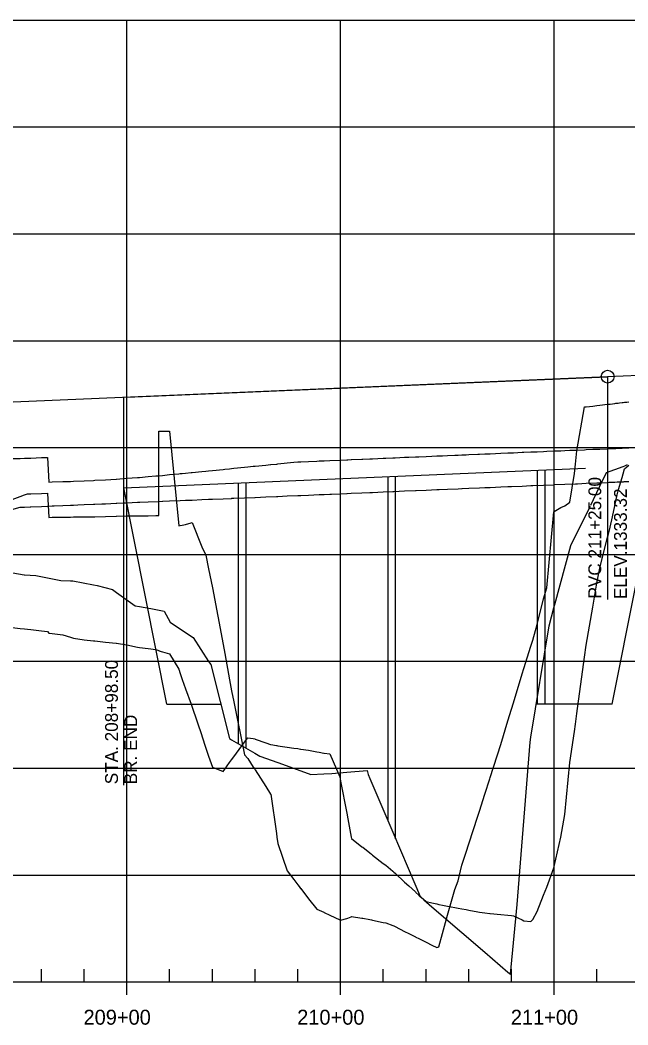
# Model space of a CAD drawing. Extents: x 1371206 to 1374178, y 379328 to 381511.
# Drawn here: x 1372094.6 to 1372379.1, y 379328.3 to 379798.4 of the extents above; entities that cross this region are included whole.
import ezdxf

# ---------------------------------------------------------------- set-up
doc = ezdxf.new("R2010")
doc.units = 0
for name, color, linetype in [('30', 7, 'Continuous'), ('37', 7, 'Continuous'), ('BRIDGE', 7, 'Continuous'), ('No Plot', 7, 'Continuous'), ('R_Exist Surface', 7, 'Continuous'), ('R_Profile Work Left', 7, 'Continuous'), ('R_Profile Work Right', 7, 'Continuous'), ('R_Vert Alg', 7, 'Continuous'), ('R_Vert Alg Annot', 7, 'Continuous')]:
    doc.layers.add(name, color=color, linetype=linetype)

msp = doc.modelspace()

# ---------------------------------------------------------------- linework, layer by layer
at = {"layer": '37'}
for p, q in [((1371244.63, 379798.35), (1374144.63, 379798.35)), ((1371244.63, 379798.35), (1374144.63, 379798.35)), ((1372144.63, 379348.35), (1372144.63, 379798.35)), ((1372244.63, 379348.35), (1372244.63, 379798.35)), ((1372344.63, 379348.35), (1372344.63, 379798.35)), ((1371244.63, 379748.35), (1374144.63, 379748.35)), ((1371244.63, 379698.35), (1374144.63, 379698.35)), ((1371244.63, 379648.35), (1374144.63, 379648.35)), ((1371244.63, 379598.35), (1372944.63, 379598.35)), ((1371244.63, 379598.35), (1374144.63, 379598.35)), ((1371244.63, 379548.35), (1374144.63, 379548.35)), ((1371244.63, 379498.35), (1374144.63, 379498.35)), ((1371244.63, 379448.35), (1374144.63, 379448.35)), ((1371244.63, 379398.35), (1374144.63, 379398.35)), ((1372104.63, 379348.35), (1372104.63, 379354.35)), ((1372124.63, 379348.35), (1372124.63, 379354.35)), ((1372164.63, 379348.35), (1372164.63, 379354.35)), ((1372184.63, 379348.35), (1372184.63, 379354.35)), ((1372204.63, 379348.35), (1372204.63, 379354.35)), ((1372224.63, 379348.35), (1372224.63, 379354.35)), ((1372264.63, 379348.35), (1372264.63, 379354.35)), ((1372284.63, 379348.35), (1372284.63, 379354.35)), ((1372304.63, 379348.35), (1372304.63, 379354.35)), ((1372324.63, 379348.35), (1372324.63, 379354.35)), ((1372364.63, 379348.35), (1372364.63, 379354.35)), ((1371244.63, 379348.35), (1374144.63, 379348.35)), ((1372144.63, 379342.35), (1372144.63, 379348.35)), ((1372244.63, 379342.35), (1372244.63, 379348.35)), ((1372344.63, 379342.35), (1372344.63, 379348.35))]:
    msp.add_line(p, q, dxfattribs=at)
at = {"layer": 'BRIDGE'}
for p, q in [((1372144.63, 379621.98), (1372369.63, 379631.52)), ((1372143.13, 379579.48), (1372359.26, 379588.65)), ((1372163.36, 379478.35), (1372143.13, 379579.49)), ((1372143.13, 379440.44), (1372143.13, 379579.3)), ((1372163.36, 379478.35), (1372188.56, 379478.35)), ((1372371.78, 379478.35), (1372336.3, 379478.35))]:
    msp.add_line(p, q, dxfattribs=at)
for points in [[(1372143.13, 379579.49), (1372143.13, 379621.93)], [(1372144.63, 379576.49), (1372144.63, 379621.49)], [(1372336.88, 379478.35), (1372336.88, 379587.7)], [(1372340.38, 379478.35), (1372340.38, 379587.85)], [(1372371.78, 379478.35), (1372394.13, 379590.12)], [(1372196.88, 379459.82), (1372196.88, 379581.76)], [(1372200.38, 379457.78), (1372200.38, 379581.91)], [(1372266.88, 379423.52), (1372266.88, 379584.73)], [(1372270.38, 379415.35), (1372270.38, 379584.88)]]:
    msp.add_lwpolyline(points, dxfattribs=at)
at = {"layer": 'No Plot'}
msp.add_lwpolyline([(1372361.76, 379571.45), (1372363.08, 379574.13), (1372366.06, 379580.34), (1372369.11, 379586.69), (1372376.84, 379589.57), (1372377.62, 379589.87), (1372379.01, 379590.36)], dxfattribs=at)
at = {"layer": 'R_Exist Surface'}
msp.add_lwpolyline([(1372085.91, 379540.75), (1372096.5, 379538.79), (1372096.68, 379538.78), (1372102.04, 379538.57), (1372107.46, 379537.4), (1372113.63, 379536.15), (1372118.23, 379535.99), (1372119.39, 379535.97), (1372129.01, 379534.19), (1372130.72, 379533.89), (1372137.9, 379531.94), (1372139.78, 379530.58), (1372148.49, 379524.37), (1372150.56, 379523.96), (1372155.76, 379522.99), (1372161.33, 379521.94), (1372162.1, 379521.81), (1372164.85, 379516.73), (1372172.11, 379511.83), (1372175.66, 379509.47), (1372182.88, 379498.31), (1372183.85, 379496.83), (1372192.67, 379462.26), (1372193.66, 379461.69), (1372204.43, 379455.43), (1372206.89, 379454), (1372215.21, 379451), (1372225.98, 379447.1), (1372230.65, 379445.41), (1372236.76, 379445.68), (1372240.52, 379445.84), (1372247.53, 379446.46), (1372257.11, 379447.28), (1372257.5, 379445.38), (1372258.31, 379443.5), (1372269.09, 379418.38), (1372279.86, 379393.16), (1372281.95, 379388.25), (1372282.56, 379387.86), (1372283.56, 379386.73), (1372286.05, 379384.61), (1372290.64, 379380.7), (1372301.41, 379371.49), (1372312.19, 379362.25), (1372322.96, 379352.98), (1372324.14, 379351.97), (1372327.31, 379384.57), (1372333.36, 379460.54), (1372333.74, 379462.8), (1372342.34, 379514.98), (1372344.51, 379523.35), (1372344.94, 379525), (1372352.44, 379552.54), (1372355.29, 379558.32), (1372361.55, 379571.02)], dxfattribs=at)
at = {"layer": 'R_Profile Work Left'}
for points in [[(1372354.19, 379586.29), (1372354.63, 379590.53), (1372355.29, 379596.85), (1372358.74, 379617.35), (1372359.63, 379617.45), (1372362.69, 379617.8), (1372364.63, 379618.02), (1372366.06, 379618.19), (1372369.63, 379618.61), (1372369.81, 379618.63), (1372370.76, 379618.74), (1372371.88, 379618.87), (1372373.01, 379619.01), (1372373.46, 379619.06), (1372374.13, 379619.14), (1372374.63, 379619.2), (1372375.26, 379619.27), (1372376.38, 379619.4), (1372376.84, 379619.46), (1372377.51, 379619.54), (1372378.63, 379619.67), (1372379.63, 379619.79)], [(1372089.63, 379573.53), (1372094.63, 379575.45), (1372096.68, 379576.23), (1372098.04, 379576.75), (1372099.63, 379576.79), (1372104.63, 379576.91), (1372107.46, 379576.97), (1372108.13, 379565.71), (1372108.15, 379565.71), (1372109.63, 379565.73), (1372114.63, 379565.8), (1372118.23, 379565.86), (1372119.63, 379565.89), (1372124.63, 379565.96), (1372129.01, 379566.02), (1372129.63, 379566.02), (1372134.63, 379566.18), (1372139.63, 379566.32), (1372139.78, 379566.32), (1372144.63, 379566.38), (1372149.63, 379566.43), (1372150.56, 379566.45), (1372154.63, 379566.49), (1372158.11, 379566.56), (1372159.5, 379566.62), (1372159.63, 379606.03)], [(1372159.63, 379606.03), (1372161.33, 379606.06), (1372164.63, 379606.09)], [(1372164.63, 379606.09), (1372168.88, 379561.74), (1372169.63, 379561.9), (1372170.57, 379562.1), (1372172.11, 379562.43), (1372174.63, 379563.08), (1372175.16, 379563.28), (1372179.63, 379551.95)], [(1372089.63, 379569.06), (1372094.63, 379570.4), (1372096.68, 379570.49), (1372096.73, 379570.49), (1372099.38, 379570.61), (1372099.63, 379570.62), (1372104.63, 379570.83), (1372107.46, 379570.95), (1372107.51, 379570.95), (1372109.63, 379571.04), (1372110.54, 379571.08), (1372114.63, 379571.25), (1372118.23, 379571.41), (1372118.29, 379571.41), (1372119.63, 379571.46), (1372121.7, 379571.55), (1372124.63, 379571.68), (1372129.01, 379571.86), (1372129.07, 379571.87), (1372129.63, 379571.89), (1372132.86, 379572.03), (1372134.63, 379572.1), (1372139.63, 379572.31), (1372139.78, 379572.32), (1372139.85, 379572.32), (1372143.13, 379572.46), (1372144.02, 379572.5), (1372144.63, 379572.52), (1372149.63, 379572.74), (1372150.56, 379572.78), (1372150.63, 379572.78), (1372154.63, 379572.95), (1372159.63, 379573.16), (1372161.33, 379573.23), (1372161.41, 379573.24), (1372164.55, 379573.37), (1372164.63, 379573.37), (1372169.63, 379573.58), (1372172.11, 379573.69), (1372172.19, 379573.69), (1372174.63, 379573.8), (1372175.16, 379573.82), (1372179.63, 379574.01), (1372182.88, 379574.15), (1372182.98, 379574.15), (1372184.63, 379574.22), (1372189.63, 379574.43), (1372193.66, 379574.6), (1372193.76, 379574.61), (1372194.63, 379574.64), (1372199.63, 379574.86), (1372204.43, 379575.06), (1372204.54, 379575.06), (1372204.63, 379575.07), (1372209.63, 379575.28), (1372214.63, 379575.49), (1372215.21, 379575.52), (1372215.32, 379575.52), (1372219.63, 379575.7), (1372224.63, 379575.92), (1372225.18, 379575.94), (1372225.98, 379575.97), (1372226.1, 379575.98), (1372229.63, 379576.13), (1372234.63, 379576.34), (1372236.76, 379576.43), (1372236.88, 379576.44), (1372239.63, 379576.55), (1372240.46, 379576.59), (1372244.63, 379576.76), (1372247.53, 379576.89), (1372247.66, 379576.89), (1372249.63, 379576.98), (1372254.63, 379577.19), (1372258.31, 379577.34), (1372258.44, 379577.35), (1372259.63, 379577.4), (1372264.63, 379577.61), (1372269.09, 379577.8), (1372269.23, 379577.81), (1372269.63, 379577.82), (1372274.63, 379578.04), (1372279.63, 379578.25), (1372279.86, 379578.26), (1372280.01, 379578.26), (1372284.63, 379578.46), (1372289.63, 379578.67), (1372290.64, 379578.72), (1372290.79, 379578.72), (1372294.63, 379578.88), (1372299.63, 379579.1), (1372301.41, 379579.17), (1372301.57, 379579.18), (1372304.63, 379579.31), (1372309.63, 379579.52), (1372312.19, 379579.63), (1372312.35, 379579.64), (1372314.63, 379579.73), (1372319.63, 379579.94), (1372322.96, 379580.09), (1372323.13, 379580.09), (1372324.63, 379580.16), (1372329.63, 379580.37), (1372333.74, 379580.54), (1372333.91, 379580.55), (1372334.63, 379580.58), (1372339.63, 379580.79), (1372344.51, 379581), (1372344.63, 379581), (1372344.69, 379581.01), (1372349.63, 379581.22), (1372354.63, 379581.43), (1372355.29, 379581.46), (1372355.48, 379581.46), (1372359.63, 379581.64), (1372364.63, 379581.85), (1372366.06, 379581.91), (1372366.26, 379581.92), (1372369.63, 379582.06), (1372370.43, 379582.1), (1372370.75, 379582.11), (1372371.86, 379582.16), (1372372.97, 379582.21), (1372374.09, 379582.26), (1372374.63, 379582.29), (1372375.2, 379582.31), (1372376.32, 379582.37), (1372376.84, 379582.39), (1372377.04, 379582.4), (1372377.43, 379582.42), (1372378.55, 379582.48), (1372379.63, 379582.53)], [(1372341.16, 379532.67), (1372344.51, 379568.37), (1372344.63, 379568.44), (1372347.67, 379570.34), (1372349.63, 379571.03), (1372351.92, 379572.85), (1372354.19, 379586.29)], [(1372179.63, 379551.95), (1372179.65, 379551.92), (1372181.64, 379548.05), (1372182.88, 379541.63), (1372184.63, 379532.67), (1372189.63, 379506.17), (1372190.42, 379501.95), (1372192.71, 379489.67), (1372193.66, 379484.57), (1372194.63, 379479.38), (1372199.63, 379454.67), (1372201.18, 379452.88), (1372203.77, 379448.86), (1372204.43, 379447.83), (1372204.63, 379447.53), (1372209.63, 379439.77), (1372211.91, 379436.24), (1372211.95, 379436.18), (1372214.63, 379417.74), (1372214.84, 379416.02), (1372215.21, 379413.06), (1372219.63, 379400.41), (1372222.72, 379396.33), (1372224.63, 379393.8), (1372225.18, 379393.08), (1372225.91, 379392.1), (1372225.98, 379392.01), (1372229.63, 379387.16), (1372233.48, 379382.44), (1372234.63, 379381.91), (1372236.76, 379380.92), (1372236.98, 379380.82), (1372239.63, 379379.59), (1372244.25, 379377.45), (1372244.63, 379377.27), (1372247.53, 379378.05), (1372248.05, 379378.26), (1372249.63, 379378.89), (1372249.74, 379378.93), (1372254.63, 379378.26), (1372255.02, 379378.18), (1372258.31, 379377.51), (1372259.12, 379377.35), (1372259.63, 379377.24), (1372264.63, 379376.22), (1372265.79, 379375.98), (1372269.09, 379374.81), (1372269.63, 379374.54), (1372270.19, 379374.26), (1372274.63, 379372.01), (1372276.55, 379371.03), (1372279.63, 379369.47), (1372279.86, 379369.36), (1372281.26, 379368.65), (1372284.63, 379366.94), (1372287.32, 379365.58), (1372289.63, 379364.41), (1372290.64, 379364.73), (1372292.33, 379370.99), (1372294.63, 379379.52), (1372298.09, 379391.6), (1372299.63, 379395.72), (1372301.41, 379403.02), (1372303.4, 379409.11), (1372304.63, 379412.91), (1372308.86, 379425.93), (1372309.63, 379428.32), (1372312.19, 379436.23), (1372314.47, 379443.39), (1372314.63, 379443.95), (1372319.62, 379459.46), (1372319.63, 379459.48), (1372322.96, 379470.45), (1372324.63, 379475.96), (1372325.53, 379478.95), (1372329.63, 379492.51), (1372330.39, 379494.92), (1372333.74, 379505.39), (1372334.63, 379508.19), (1372336.6, 379515.53), (1372339.63, 379527.55), (1372341.16, 379532.67)]]:
    msp.add_lwpolyline(points, dxfattribs=at)
at = {"layer": 'R_Profile Work Right'}
for points in [[(1372089.63, 379593.17), (1372094.63, 379593.31), (1372096.68, 379593.37), (1372098.04, 379593.42), (1372099.63, 379593.47), (1372104.63, 379593.66), (1372107.46, 379593.78), (1372108.13, 379582.21), (1372108.15, 379582.21), (1372109.63, 379582.25), (1372114.63, 379582.41), (1372118.23, 379582.54), (1372119.63, 379582.59), (1372124.63, 379582.81), (1372129.01, 379583.02), (1372129.63, 379583.05), (1372134.63, 379583.33), (1372139.63, 379583.64), (1372139.78, 379583.65), (1372144.63, 379583.98), (1372149.63, 379584.35), (1372150.56, 379584.42), (1372154.63, 379584.76), (1372158.11, 379585.06), (1372159.5, 379585.18), (1372159.63, 379585.19), (1372161.33, 379585.36), (1372164.63, 379585.69), (1372168.88, 379586.11), (1372169.63, 379586.19), (1372170.57, 379586.28), (1372172.11, 379586.43), (1372174.63, 379586.68), (1372175.16, 379586.74), (1372179.63, 379587.18), (1372179.65, 379587.18), (1372181.64, 379587.38), (1372182.88, 379587.5), (1372184.63, 379587.68), (1372189.63, 379588.17), (1372190.42, 379588.25), (1372192.71, 379588.48), (1372193.66, 379588.57), (1372194.63, 379588.67), (1372199.63, 379589.16), (1372201.18, 379589.32), (1372203.77, 379589.58), (1372204.43, 379589.64), (1372204.63, 379589.66), (1372209.63, 379590.16), (1372211.91, 379590.38), (1372211.95, 379590.39), (1372214.63, 379590.65), (1372214.84, 379590.67), (1372215.21, 379590.71), (1372219.63, 379591.15), (1372222.72, 379591.46), (1372224.63, 379591.65), (1372225.18, 379591.7), (1372225.91, 379591.73), (1372225.98, 379591.73), (1372229.63, 379591.89), (1372233.48, 379592.05), (1372234.63, 379592.1), (1372236.76, 379592.19), (1372236.98, 379592.2), (1372239.63, 379592.31), (1372244.25, 379592.51), (1372244.63, 379592.53), (1372247.53, 379592.65), (1372248.05, 379592.67), (1372249.63, 379592.74), (1372249.74, 379592.74), (1372254.63, 379592.95), (1372255.02, 379592.97), (1372258.31, 379593.11), (1372259.12, 379593.14), (1372259.63, 379593.16), (1372264.63, 379593.37), (1372265.79, 379593.42), (1372269.09, 379593.56), (1372269.63, 379593.59), (1372270.19, 379593.61), (1372274.63, 379593.8), (1372276.55, 379593.88), (1372279.63, 379594.01), (1372279.86, 379594.02), (1372281.26, 379594.08), (1372284.63, 379594.22), (1372287.32, 379594.34), (1372289.63, 379594.44), (1372290.64, 379594.48), (1372292.33, 379594.55), (1372294.63, 379594.65), (1372298.09, 379594.79), (1372299.63, 379594.86), (1372301.41, 379594.94), (1372303.4, 379595.02), (1372304.63, 379595.07), (1372308.86, 379595.25), (1372309.63, 379595.28), (1372312.19, 379595.39), (1372314.47, 379595.49), (1372314.63, 379595.5), (1372319.62, 379595.71), (1372319.63, 379595.71), (1372322.96, 379595.85), (1372324.63, 379595.92), (1372325.53, 379595.96), (1372329.63, 379596.13), (1372330.39, 379596.17), (1372333.74, 379596.31), (1372334.63, 379596.35), (1372336.6, 379596.43), (1372339.63, 379596.56), (1372341.16, 379596.62), (1372344.51, 379596.76), (1372344.63, 379596.77), (1372347.67, 379596.9), (1372349.63, 379596.98), (1372351.92, 379597.08), (1372354.19, 379597.18), (1372354.63, 379597.19), (1372355.29, 379597.22), (1372358.74, 379597.37), (1372359.63, 379597.41), (1372362.69, 379597.54), (1372364.63, 379597.62), (1372366.06, 379597.68), (1372369.63, 379597.83), (1372369.81, 379597.84), (1372370.76, 379597.88), (1372371.88, 379597.93), (1372373.01, 379597.98), (1372373.46, 379598), (1372374.13, 379598.03), (1372374.63, 379598.05), (1372375.26, 379598.08), (1372376.38, 379598.14), (1372376.84, 379598.16), (1372377.51, 379598.19), (1372378.63, 379598.24), (1372379.63, 379598.29)], [(1372089.63, 379514.3), (1372094.63, 379513.78), (1372096.68, 379513.53), (1372098.04, 379513.36), (1372099.63, 379513.17), (1372104.63, 379512.59), (1372107.46, 379512.31), (1372108.13, 379511.5), (1372108.15, 379511.5), (1372109.63, 379511.35), (1372114.63, 379510.72), (1372118.23, 379509.66), (1372119.63, 379509.25), (1372124.63, 379508.45), (1372129.01, 379507.97), (1372129.63, 379507.91), (1372134.63, 379507.37), (1372139.63, 379506.83), (1372139.78, 379506.81), (1372144.63, 379506.03), (1372149.63, 379504.98), (1372150.56, 379504.86), (1372154.63, 379504.33), (1372158.11, 379503.84), (1372159.5, 379503.38), (1372159.63, 379503.33), (1372161.33, 379502.77), (1372164.63, 379501.84), (1372168.88, 379494.74), (1372169.63, 379492.59), (1372170.57, 379489.92), (1372172.11, 379485.51), (1372174.63, 379478.34), (1372175.16, 379476.83), (1372179.63, 379463.63), (1372179.65, 379463.57), (1372181.64, 379457.65), (1372182.88, 379453.97), (1372184.63, 379448.82), (1372189.63, 379446.83), (1372190.42, 379447.9), (1372192.71, 379451.02), (1372193.66, 379452.32), (1372194.63, 379453.64), (1372199.63, 379460.49), (1372201.18, 379462.62), (1372203.77, 379462.31), (1372204.43, 379462.08), (1372204.63, 379462.01), (1372209.63, 379460.27), (1372211.91, 379459.48), (1372211.95, 379459.46), (1372214.63, 379458.98), (1372214.84, 379458.95), (1372215.21, 379458.89), (1372219.63, 379458.25), (1372222.72, 379457.8), (1372224.63, 379457.52), (1372225.18, 379457.44), (1372225.91, 379457.33), (1372225.98, 379457.32), (1372229.63, 379456.8), (1372233.48, 379456.08), (1372234.63, 379455.83), (1372236.76, 379455.36), (1372236.98, 379455.31), (1372239.63, 379455.02), (1372244.25, 379444.27), (1372244.63, 379442.31), (1372247.53, 379427.28), (1372248.05, 379424.61), (1372249.63, 379416.02), (1372249.74, 379415.46), (1372254.63, 379411.63), (1372255.02, 379411.33), (1372258.31, 379408.76), (1372259.12, 379408.13), (1372259.63, 379407.73), (1372264.63, 379403.84), (1372265.79, 379402.94), (1372269.09, 379400.21), (1372269.63, 379399.71), (1372270.19, 379399.19), (1372274.63, 379395.07), (1372276.55, 379393.29), (1372279.63, 379390.45), (1372279.86, 379390.24), (1372281.26, 379388.94), (1372284.63, 379385.94), (1372287.32, 379385.35), (1372289.63, 379384.85), (1372290.64, 379384.63), (1372292.33, 379384.26), (1372294.63, 379383.75), (1372298.09, 379383.18), (1372299.63, 379382.94), (1372301.41, 379382.61), (1372303.4, 379382.22), (1372304.63, 379381.98), (1372308.86, 379381.14), (1372309.63, 379380.99), (1372312.19, 379380.61), (1372314.47, 379380.4), (1372314.63, 379380.38), (1372319.62, 379379.92), (1372319.63, 379379.92), (1372322.96, 379379.61), (1372324.63, 379379.45), (1372325.53, 379379.35), (1372329.63, 379377.37), (1372330.39, 379377), (1372333.74, 379376.67), (1372334.63, 379377.59), (1372336.6, 379381.3), (1372339.63, 379388.93), (1372341.16, 379392.77), (1372344.51, 379401.81), (1372344.63, 379402.36), (1372347.67, 379416.12), (1372349.63, 379426.68), (1372351.92, 379451.01), (1372354.19, 379465.53), (1372354.63, 379468.91), (1372355.29, 379473.95), (1372358.74, 379500.3), (1372359.63, 379505.9), (1372362.69, 379523.67), (1372364.63, 379534.89), (1372366.06, 379541.92), (1372369.63, 379556.48), (1372369.81, 379557.22), (1372370.76, 379561.07), (1372371.88, 379566.01), (1372373.01, 379571.16), (1372373.46, 379573.23), (1372374.13, 379576.23), (1372374.63, 379578.04), (1372375.26, 379580.31), (1372376.38, 379584.4), (1372376.84, 379586.04), (1372377.51, 379588.47), (1372378.63, 379589.32), (1372379.63, 379590.06)]]:
    msp.add_lwpolyline(points, dxfattribs=at)
at = {"layer": 'R_Vert Alg'}
msp.add_line((1371594.63, 379598.67), (1372369.63, 379631.53), dxfattribs=at)
msp.add_lwpolyline([(1372369.63, 379631.53), (1372376.92, 379631.86), (1372384.21, 379632.24)], dxfattribs=at)
msp.add_circle((1372369.63, 379631.53), 3, dxfattribs=at)
at = {"layer": 'R_Vert Alg Annot'}
msp.add_line((1372369.63, 379631.53), (1372369.63, 379527.28), dxfattribs=at)

# ---------------------------------------------------------------- texts
at = {"layer": '30'}
for s, p in [('209+00', (1372124.32, 379328.35)), ('210+00', (1372224.32, 379328.35)), ('211+00', (1372324.32, 379328.35))]:
    msp.add_text(s, height=7, dxfattribs=at).set_placement(p)
at = {"layer": 'BRIDGE'}
for s, p in [('STA. 208+98.50', (1372140.42, 379440.84)), ('BR. END', (1372149.42, 379440.84))]:
    msp.add_text(s, height=6, rotation=90, dxfattribs=at).set_placement(p)
at = {"layer": 'R_Vert Alg Annot'}
for s, p in [('PVC 211+25.00', (1372366.63, 379527.71)), ('ELEV.1333.32', (1372378.63, 379527.46))]:
    msp.add_text(s, height=6, rotation=90, dxfattribs=at).set_placement(p)

doc.saveas('drawing.dxf')
